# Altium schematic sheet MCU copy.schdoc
size 293 x 185 mm
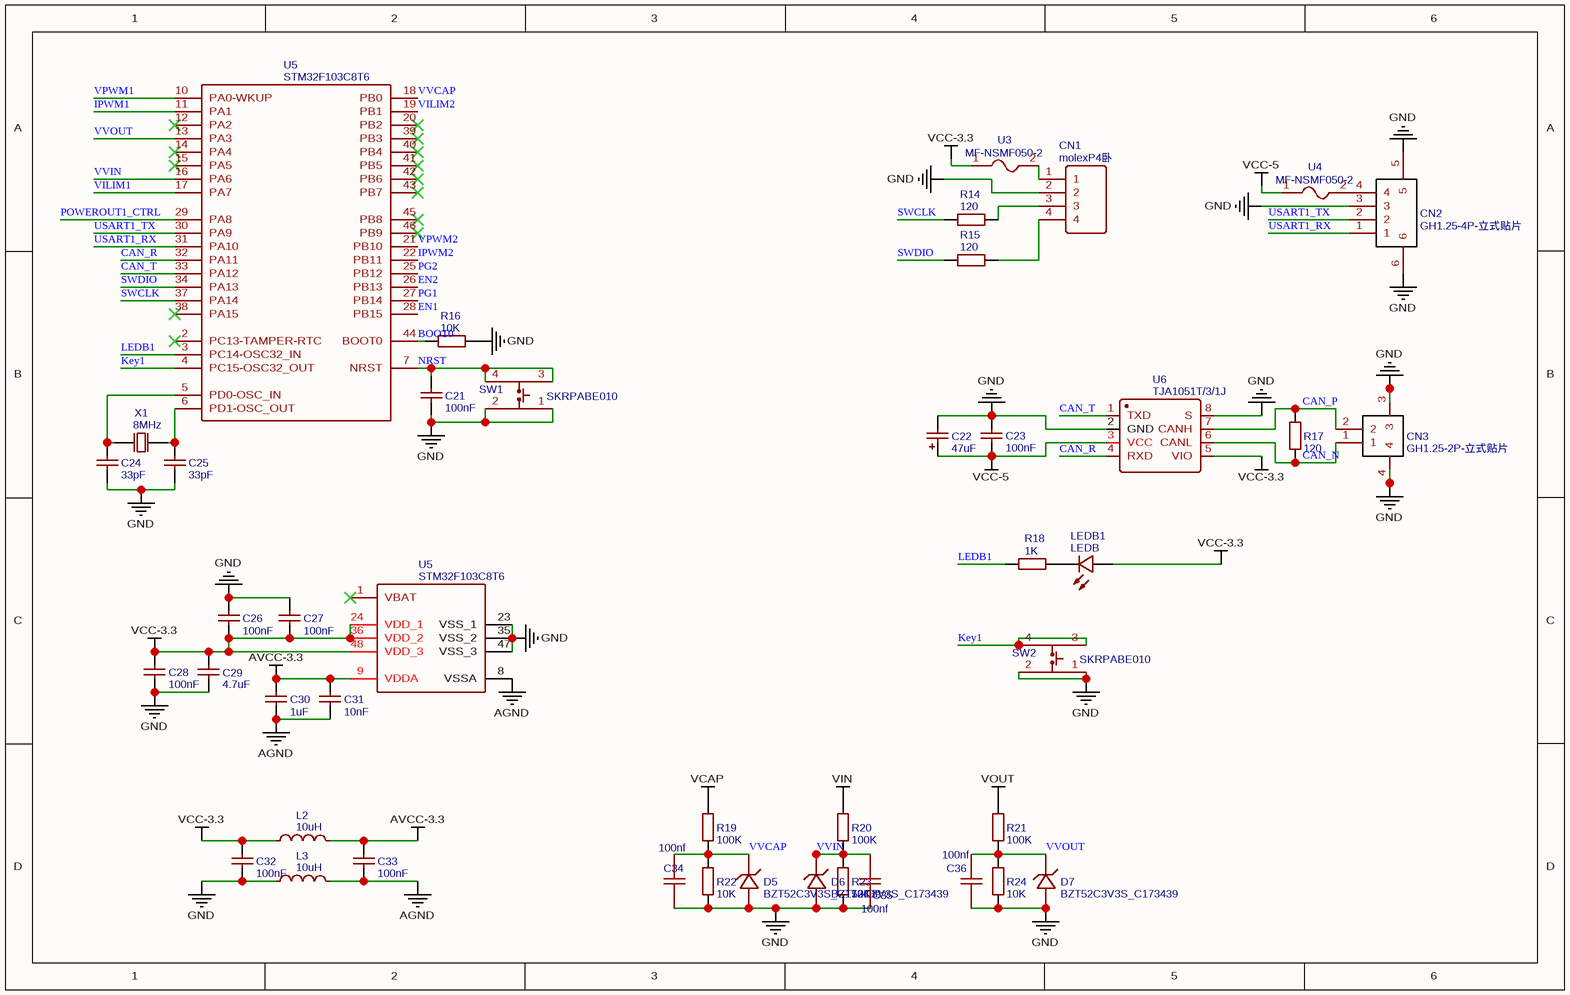
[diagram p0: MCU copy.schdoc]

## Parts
(Parts that share a designator on the sheet are numbered #1, #2 ... from top to bottom, then left to right.)
C21  100nF  [C0603]
C22  47uF  [CASE-A_3216]
C23  100nF  [R0603]
C24  33pF  [C0603]
C25  33pF  [C0603]
C26  100nF  [C0603]
C27  100nF  [C0603]
C28  100nF  [C0603]
C29  4.7uF  [C0603]
C30  1uF  [C0603]
C31  10nF  [C0603]
C32  100nF  [C0603]
C33  100nF  [C0603]
C34  100nf  [C0603]
C35  100nf  [C0603]
C36  100nf  [C0603]
CN1  molexP4卧  [SMD-10.15X4.8-4P]
CN2  GH1.25-4P-立式贴片  [SMD-1.25MM-4P-JST-H4.05]
CN3  GH1.25-2P-立式贴片  [SMD-1.25MM-2P-JST-H4.05]
D5  BZT52C3V3S_C173439  [SOD-323_L1.8-W1.3-LS2.5-RD]
D6  BZT52C3V3S_C173439  [SOD-323_L1.8-W1.3-LS2.5-RD]
D7  BZT52C3V3S_C173439  [SOD-323_L1.8-W1.3-LS2.5-RD]
L2  10uH  [L0603]
L3  10uH  [L0603]
LEDB1  LEDB  [LED-0603]
R14  120  [R0402]
R15  120  [R0402]
R16  10K  [R0402]
R17  120  [R0402]
R18  1K  [R0603]
R19  100K  [R0402]
R20  100K  [R0402]
R21  100K  [R0402]
R22  10K  [R0402]
R23  10K  [R0402]
R24  10K  [R0402]
SW1  SKRPABE010  [KEY-SMD-4P_L4.2-W3.2-H2.5]
SW2  SKRPABE010  [KEY-SMD-4P_L4.2-W3.2-H2.5]
U3  MF-NSMF050-2  [FUSE-1206]
U4  MF-NSMF050-2  [FUSE-1206]
U5#1  STM32F103C8T6  [LQFP-48_7X7X05P]
U5#2  STM32F103C8T6  [LQFP-48_7X7X05P]
U6  TJA1051T/3/1J  [SOIC-8_150MIL]
X1  8MHz  [SMD-5032_2P]

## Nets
AGND: C30.1 C31.1 C33.1 L3.2 U5#2.8(VSSA)
AVCC-3.3: C30.2 C31.2 C33.2 L2.2 U5#2.9(VDDA)
GND: C21.1 C22.2 C23.2 C24.1 C25.1 C26.1 C27.2 C28.1 C29.1 C32.1 C34.1 C35.1 C36.1 CN1.2 CN2.3 CN2.5 CN2.6 CN3.3 CN3.4 D5.2 D6.2 D7.2 L3.1 R16.1 R22.1 R23.1 R24.1 SW1.1 SW1.2 SW2.1 SW2.2 U5#2.23(VSS_1) U5#2.35(VSS_2) U5#2.47(VSS_3) U6.2(GND) U6.8(S)
VCAP: R19.2
VCC-3.3: C26.2 C27.1 C28.2 C29.2 C32.2 L2.1 LEDB1.1(A) U3.1 U5#2.24(VDD_1) U5#2.36(VDD_2) U5#2.48(VDD_3) U6.5(VIO)
VCC-5: C22.1 C23.1 U4.1 U6.3(VCC)
VIN: R20.2
VOUT: R21.2
BOOT0: R16.2 U5#1.44(BOOT0)
CAN_N: CN3.1 R17.2 U6.6(CANL)
CAN_P: CN3.2 R17.1 U6.7(CANH)
CAN_R: U5#1.32(PA11) U6.4(RXD)
CAN_T: U5#1.33(PA12) U6.1(TXD)
EN1: U5#1.28(PB15)
EN2: U5#1.26(PB13)
IPWM1: U5#1.11(PA1)
IPWM2: U5#1.22(PB11)
Key1: SW2.3 SW2.4 U5#1.4(PC15-OSC32_OUT)
LEDB1: R18.1 U5#1.3(PC14-OSC32_IN)
NRST: C21.2 SW1.3 SW1.4 U5#1.7(NRST)
PG1: U5#1.27(PB14)
PG2: U5#1.25(PB12)
POWEROUT1_CTRL: U5#1.29(PA8)
SWCLK: R14.2 U5#1.37(PA14)
SWDIO: R15.2 U5#1.34(PA13)
USART1_RX: CN2.1 U5#1.31(PA10)
USART1_TX: CN2.2 U5#1.30(PA9)
VILIM1: U5#1.17(PA7)
VILIM2: U5#1.19(PB1)
VPWM1: U5#1.10(PA0-WKUP)
VPWM2: U5#1.21(PB10)
VVCAP: C34.2 D5.1 R19.1 R22.2 U5#1.18(PB0)
VVIN: C35.2 D6.1 R20.1 R23.2 U5#1.16(PA6)
VVOUT: C36.2 D7.1 R21.1 R24.2 U5#1.13(PA3)
NetC24_2: C24.2 U5#1.5(PD0-OSC_IN) X1.1(OSC1)
NetC25_2: C25.2 U5#1.6(PD1-OSC_OUT) X1.2(OSC2)
NetCN1_1: CN1.1 U3.2
NetCN1_3: CN1.3 R14.1
NetCN1_4: CN1.4 R15.1
NetCN2_4: CN2.4 U4.2
NetLEDB1_2: LEDB1.2(C) R18.2

Not connected (* = marked no-connect by the designer): U5#1 2(PC13-TAMPER-RTC)* 12(PA2)* 14(PA4)* 15(PA5)* 20(PB2)* 38(PA15)* 39(PB3)* 40(PB4)* 41(PB5)* 42(PB6)* 43(PB7)* 45(PB8)* 46(PB9)*; U5#2 1(VBAT)*

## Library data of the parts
C21 C23 C26-C28 C32 C33 = 100nF: BOM_Manufacturer Part: CL05B104KO5NNNC; BOM_Manufacturer: SAMSUNG; nameAlias: Capacitance
C22 = 47uF: BOM_Manufacturer: Xiangyee; BOM_Manufacturer Part: CA45-A010K476T; nameAlias: Capacitance; Contributor: LCSC
C24 C25 = 33pF: BOM_Manufacturer Part: CL05C330JB5NNNC; BOM_Manufacturer: SAMSUNG; nameAlias: Capacitance
C29 = 4.7uF: BOM_Manufacturer Part: CL10A475KO8NNNC; BOM_Manufacturer: SAMSUNG; nameAlias: Capacitance; SMT Type: Basic
C30 = 1uF: BOM_Manufacturer Part: CL10A105KB8NNNC; BOM_Manufacturer: SAMSUNG; nameAlias: Capacitance
C31 = 10nF: BOM_Manufacturer Part: CL05B103KB5NNNC; BOM_Manufacturer: SAMSUNG; nameAlias: Capacitance
C34-C36 = 100nf: nameAlias: Value(F)
CN1 = molexP4卧: BOM_Manufacturer: MOLEX; BOM_Manufacturer Part: 532610471
CN2 = GH1.25-4P-立式贴片: BOM_Manufacturer: JST Sales America; BOM_Manufacturer Part: BM04B-GHS-TBT(LF)(SN); Contributor: LCSC
CN3 = GH1.25-2P-立式贴片: BOM_Manufacturer: JST Sales America; BOM_Manufacturer Part: BM02B-GHS-TBT (LF)(SN); Contributor: LCSC
D5-D7 = BZT52C3V3S_C173439: BOM_Manufacturer: (MDD) Jiangsu Yutai Elec; Contributor: LCSC; SMT Type: Extend
L2 L3 = 10uH: BOM_Manufacturer: Sunlord; BOM_Manufacturer Part: SDFL2012S100KTF; nameAlias: Inductance; SMT Type: Basic
LEDB1 = LEDB: BOM_Manufacturer: EVERLIGHT
R14 R15 R17 = 120: BOM_Manufacturer: UniOhm; BOM_Manufacturer Part: 0402WGF1200TCE; nameAlias: Resistance (Ohms)
R16 R22-R24 = 10K: BOM_Manufacturer: UniOhm; BOM_Manufacturer Part: 0402WGF1002TCE; nameAlias: Resistance (Ohms); SMT Type: Basic
R18 = 1K: BOM_Manufacturer: UniOhm; BOM_Manufacturer Part: 0402WGF1001TCE; nameAlias: Resistance (Ohms); SMT Type: Basic
R19-R21 = 100K: BOM_Manufacturer: UniOhm; BOM_Manufacturer Part: 0402WGF1003TCE; nameAlias: Resistance (Ohms); SMT Type: Basic
SW1 SW2 = SKRPABE010: BOM_Manufacturer: ALPS
U3 U4 = MF-NSMF050-2: BOM_Manufacturer: BOURNS
U5#1 U5#2 = STM32F103C8T6: BOM_Manufacturer: ST; subpart_no: 1; tags: STM32
U6 = TJA1051T/3/1J: BOM_Manufacturer: NXP
X1 = 8MHz: BOM_Manufacturer: Yangxing Tech; BOM_Manufacturer Part: X50328MSD2GC; nameAlias: Frequency; Contributor: LCSC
